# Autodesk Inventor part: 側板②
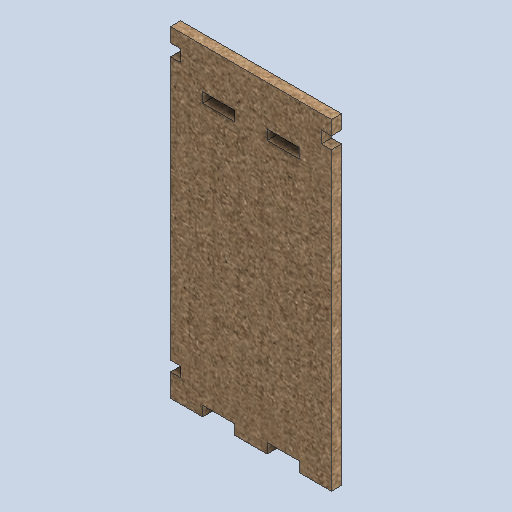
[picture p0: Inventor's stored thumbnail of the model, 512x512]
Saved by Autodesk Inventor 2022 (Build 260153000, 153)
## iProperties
Created: 2024-11
Part Number: 側板②
Material: MDF 中密度繊維ボード
Document SubType Name: Modeling
Designer: shimizu
Density: 0.8 g/cm^3
Appearance: ダンボール - 段ボール紙
Author: shimizu
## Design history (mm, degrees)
sketch "スケッチ1"
  geometry: L1 (-20.243, 58.107)-(19.757, 58.107); L2 (-4.243, -21.893)-(-4.243, -19.393); L3 (-4.243, -19.393)-(-12.243, -19.393); L4 (-12.243, -19.393)-(-12.243, -21.893); L5 (11.757, -21.893)-(11.757, -19.393); L6 (11.757, -19.393)-(3.757, -19.393); L7 (3.757, -19.393)-(3.757, -21.893); L8 (-12.243, 48.107)-(-4.243, 48.107); L9 (-4.243, 48.107)-(-4.243, 45.607); L10 (-4.243, 45.607)-(-12.243, 45.607); L11 (-12.243, 45.607)-(-12.243, 48.107); L12 (3.757, 48.107)-(11.757, 48.107); L13 (11.757, 48.107)-(11.757, 45.607); L14 (11.757, 45.607)-(3.757, 45.607); L15 (3.757, 45.607)-(3.757, 48.107); L16 (-12.243, -21.893)-(-20.243, -21.893); L17 (19.757, -21.893)-(11.757, -21.893); L18 (3.757, -21.893)-(-4.243, -21.893); L19 (-20.243, 54.607)-(-17.743, 54.607); L20 (-17.743, 54.607)-(-17.743, 51.607); L21 (-17.743, 51.607)-(-20.243, 51.607); L22 (19.757, 54.607)-(17.257, 54.607); L23 (17.257, 54.607)-(17.257, 51.607); L24 (17.257, 51.607)-(19.757, 51.607); L25 (-20.243, -21.893)-(-20.243, 51.607); L26 (-20.243, 54.607)-(-20.243, 58.107); L27 (19.757, 58.107)-(19.757, 54.607); L28 (19.757, 51.607)-(19.757, -21.893); L29 (19.757, 42.426)-(17.257, 42.426); L30 (17.257, 42.426)-(17.257, 39.926); L31 (17.257, 39.926)-(19.757, 39.926); L32 (19.757, 39.926)-(19.757, 42.426); L33 (-20.243, -13.703)-(-17.743, -13.703); L34 (-17.743, -13.703)-(-17.743, -16.213); L35 (-17.743, -16.213)-(-20.243, -16.213); L36 (-20.243, -16.213)-(-20.243, -13.703); 3 further points
  constraints: 72 end point, 19 parallel, 8 perpendicular, 7 horizontal, 2 point on line
  dimensions: "d27" = 80 distance between parallel lines of L17 L1; "d28" = 40 distance between parallel lines of L25 L28; "d29" = 3.181 distance between parallel lines of L29 L14; "d30" = 2.5 distance of L30.end L31.end; "d31" = 2.5 distance between parallel lines of L16 L3; "d32" = 3.18 distance between parallel lines of L3 L35; "d33" = 2.51 distance of L33.end L34.end; "d34" = 2.5 distance between parallel lines of L36 L34; "d35" = 2.5 distance between parallel lines of L31 L29
extrude "押し出し1" new body sketch "スケッチ1" distance "d13" = 2.5; taper "d14" = 0 deg
node "ソリッド1"
